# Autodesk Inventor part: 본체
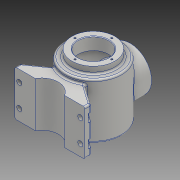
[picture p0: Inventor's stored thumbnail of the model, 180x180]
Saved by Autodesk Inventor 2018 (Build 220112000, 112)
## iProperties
Created: 2021-04
Part Number: 본체
Material: 알루미늄 6061
Document SubType Name: Modeling
Designer: home
Density: 2.7 g/cm^3
Appearance: 알루미늄 - 평지
Mass: 1641.59 g
Surface Area: 1039.47 cm^2
Volume: 607.998 cm^3
Author: home
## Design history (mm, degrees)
sketch "스케치1"
  geometry: L1 (0, 0)-(77, 0); L2 (127, 48)-(127, -48.336); L3 (127, 48)-(115, 48); L4 (115, 60)-(115, 48); L5 (115, 60)-(77, 60); L6 (77, 60)-(77, -60); L7 (104, 38)-(104, 60); L8 (117, 38)-(117, -41.916); L9 (104, 38)-(117, 38); A1 r 113 centre (77, 53) between (77, -60) and (127, -48.336); A2 r 103 centre (77, 53) between (77, -50) and (117, -41.916); 2 further points
  constraints: 18 end point, 4 point on circle, 3 horizontal, 2 centre point, 2 horizontal alignment, 2 perpendicular, 2 point on line, 2 vertical, 1 coincident, 1 midpoint, 1 parallel
  dimensions: "d6" = 77 distance of L1.start L1.end; "d7" = 113 radius of A1; "d12" = 120 distance of L5.end L6.end; "d22" = 40 distance between parallel lines of L6 L8; "d25" = 10 radial gap between concentric circles of A1 A2; "d124" = 100 diameter of L2 L6; "d125" = 12 distance between parallel lines of L4 L2; "d126" = 23 distance between parallel lines of L7 L2; "d127" = 10 distance between parallel lines of L9 L3; "d128" = 22 distance between parallel lines of L9 L5; "d129" = 86.33607 distance from line of L2.end L9; "d130" = 32.23748 distance from line of point (94.763, 0) L2
revolve "회전1" sketch "스케치1" stored, may be unused: angle "d40" = 90 deg
sketch "스케치2"
  geometry: L1 (62, 10)-(26.694, 34.722); L2 (-62, 10)-(-62, 0); L3 (62, 10)-(62, 0); L4 (0, 0)-(0, 15); L5 (-62, 0)-(-25.981, 0); L6 (25.981, 0)-(62, 0); L7 (-62, 10)-(-26.694, 34.722); A1 r 50 centre (0, 77) between (26.694, 34.722) and (-33.723, 40.084) reference; A2 r 30 centre (0, -15) between (25.981, 0) and (-25.981, 0); 2 further points
  constraints: 14 end point, 6 point on circle, 3 coincident, 2 horizontal, 2 perpendicular, 2 vertical, 1 centre point, 1 vertical alignment
  dimensions: "d41" = 124 distance of L2.end L3.end; "d48" = 15 distance of L4.start L4.end; "d115" = 55 deg angle of L3 L1; "d116" = 10 distance from line of L1.start L6; "d117" = 10 distance from line of L5 L2.start; "d118" = 55 deg angle of L2 L7; "d119" = 30 radius of A2; "d120" = 62 distance between parallel lines of L4 L3; "d121" = 124 distance between parallel lines of L3 L2; "d122" = 19.32145 distance from line of A1.centre L1; "d123" = 95.72285 distance from line of A1.end L3
extrude "돌출1" join sketch "스케치2" stored distance "d55" = 80; taper "d56" = 0 deg
node "작업 평면1"
sketch "스케치3"
  geometry: L1 (24, 20)-(100, 20) reference; C1 r 38 at (62, -42); 2 further points
  constraints: 1 centre point, 1 midpoint, 1 vertical alignment
  dimensions: "d60" = 38 radius of C1; "d61" = 62 distance from line of L1 C1.centre
extrude "돌출2" join sketch "스케치3" stored distance "d62" = 80; taper "d63" = 0 deg
sketch "스케치4"
  geometry: C1 r 38 at (0, 0) reference; C2 r 27 at (0, 0); 1 further point
  constraints: 1 centre point, 1 coincident
  dimensions: "d64" = 27 radius of C2
extrude "돌출3" cut sketch "스케치4" stored distance "d65" = 80; taper "d66" = 0 deg
sketch "스케치5"
  geometry: C1 r 40 at (0, 0) reference; 2 further points
  constraints: 1 vertical alignment
  dimensions: "d68" = 32.5 distance of C1.centre point (0, 32.5)
hole "구멍1" sketch "스케치5" at (0, 32.5) diameter "d69" = 3.242; stored, may be unused: countersink angle "d73" = 90 deg, drill point angle "d75" = 118 deg; dims "d70" = 8, "d71" = 4, "d72" = 2, "d74" = 10
sketch "스케치6"
  geometry: C1 r 27 at (0, 0) reference; C2 r 38 at (0, 0) reference; 2 further points
  constraints: 1 vertical alignment
  dimensions: "d80" = 32.5 distance of C1.centre point (0, 32.5)
hole "구멍2" sketch "스케치6" at (0, 32.5) diameter "d81" = 3.242; stored, may be unused: countersink angle "d85" = 90 deg, drill point angle "d87" = 118 deg; dims "d82" = 8, "d83" = 4, "d84" = 2, "d86" = 10
node "작업 평면3"
sketch "스케치9"
  geometry: L1 (36.019, 0)-(0, 0) reference; L2 (36.019, 0)-(36.019, 80) reference; L3 (28.019, 13)-(36.019, 13); L4 (28.019, 27)-(36.019, 27); A1 r 7 centre (28.019, 20) between (28.019, 13) and (28.019, 27); 1 further point
  constraints: 4 end point, 2 point on circle, 2 point on line, 2 tangent, 1 centre point, 1 horizontal, 1 perpendicular
  dimensions: "d99" = 7 radius of A1; "d100" = 20 distance from line of A1.centre L1; "d101" = 8 distance from line of A1.centre L2
extrude "돌출5" cut sketch "스케치9" distance "d102" = 20; taper "d103" = 0 deg
sketch "스케치10"
  geometry: L1 (28.019, -13)-(36.019, -13) reference; L2 (36.019, -27)-(28.019, -27) reference; L3 (36.019, -13)-(36.019, -27) reference; C1 r 4.5 at (28.019, -20); A1 r 7 centre (28.019, -20) between (28.019, -13) and (28.019, -27) reference; 1 further point
  constraints: 1 centre point, 1 coincident
  dimensions: "d104" = 4.5 radius of C1
extrude "돌출6" cut sketch "스케치10" extent not by distance; stored distance "d105" = 20; taper "d106" = 0 deg
node "작업 평면4"
chamfer "모따기1" distance "d111" = 1; stored, may be unused: second distance "d112" = 2, angle "d113" = 45 deg
fillet "모깎기1" dims "d114" = 3
node "작업 평면5"
sketch "스케치13"
  geometry: C1 r 48.282 at (0, 0) reference; 2 further points
  constraints: 2 coincident, 1 other
feature "엠보싱1" sketch "스케치13" dims "d6" = 77, "d7" = 113, "d12" = 120, "d22" = 40, "d25" = 10, "d124" = 100, "d125" = 12, "d126" = 23, "d127" = 10, "d128" = 22, "d129" = 86.33607, "d130" = 32.23748, "d131" = 0.5, "d132" = 0
node "솔리드1"
pattern_circular "원형 패턴1" dims angle "d77" = 360 deg
pattern_circular "원형 패턴2" dims angle "d89" = 360 deg
pattern_linear "직사각형 패턴1" dims "d109" = 40
mirror "미러1"
node "투영된 루프1"
node "투영된 루프2"
node "투영된 루프3"
node "투영된 루프5"
node "투영된 루프6"
other parameters: "d43" = 45 deg, "d44" = 45 deg, "d57" = -142, "d98" = -6, "d110" = -108
